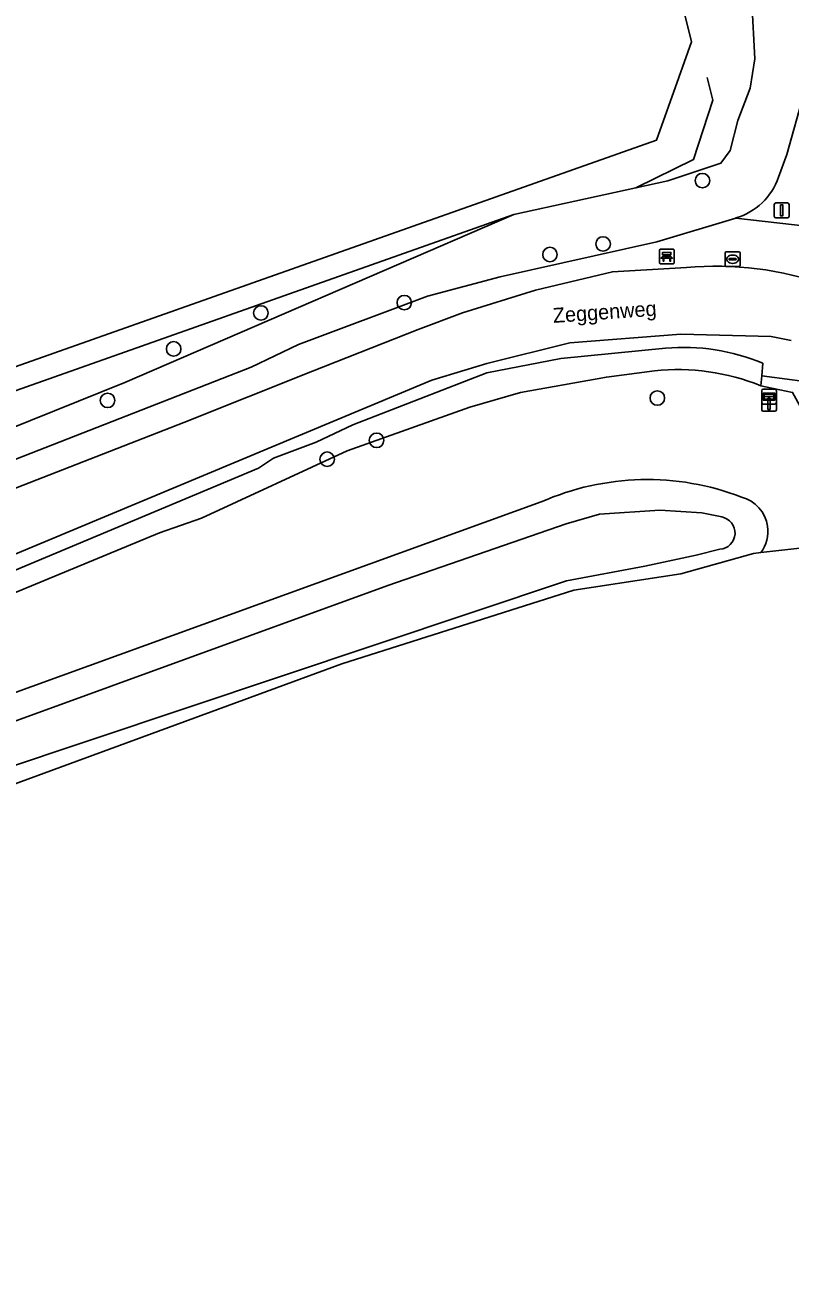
# Model space of a CAD drawing. Extents: x 164494 to 166241, y 382475 to 384495.
# Drawn here: x 164889.5 to 164941, y 383419.5 to 383503.5 of the extents above; entities that cross this region are included whole.
import ezdxf

# ---------------------------------------------------------------- set-up
doc = ezdxf.new("R2010")
doc.units = 0
for name, color, linetype in [('IMGEO_Afsluitpaal', 7, 'Continuous'), ('IMGEO_Bank', 7, 'Continuous'), ('IMGEO_Boom', 7, 'Continuous'), ('IMGEO_Bouwland', 7, 'Continuous'), ('IMGEO_Duiker', 7, 'Continuous'), ('IMGEO_Erf', 7, 'Continuous'), ('IMGEO_Grasland_overig', 7, 'Continuous'), ('IMGEO_Groenvoorziening', 7, 'Continuous'), ('IMGEO_Hek', 7, 'Continuous'), ('IMGEO_Informatiebord', 7, 'Continuous'), ('IMGEO_Loofbos', 7, 'Continuous'), ('IMGEO_Oever', 7, 'Continuous'), ('IMGEO_Openbare_ruimte_label', 7, 'Continuous'), ('IMGEO_Rijbaan_lokaal_halfverhard', 7, 'Continuous'), ('IMGEO_Rioolput', 7, 'Continuous'), ('IMGEO_Waterloop', 7, 'Continuous')]:
    doc.layers.add(name, color=color, linetype=linetype)

msp = doc.modelspace()

# ---------------------------------------------------------------- linework, layer by layer
at = {"layer": 'IMGEO_Afsluitpaal'}
for p, q in [((164939.975, 383490.643), (164939.975, 383491.443)), ((164939.975, 383491.443), (164939.975, 383490.643)), ((164940.075, 383491.543), (164940.865, 383491.543)), ((164940.865, 383491.543), (164940.075, 383491.543)), ((164940.965, 383491.443), (164940.965, 383490.643)), ((164940.965, 383490.643), (164940.965, 383491.443)), ((164940.865, 383490.543), (164940.075, 383490.543)), ((164940.075, 383490.543), (164940.865, 383490.543)), ((164939.126, 383477.607), (164939.126, 383478.407)), ((164939.126, 383478.407), (164939.126, 383477.607)), ((164939.226, 383478.507), (164940.016, 383478.507)), ((164940.016, 383478.507), (164939.226, 383478.507)), ((164940.116, 383478.407), (164940.116, 383477.607)), ((164940.116, 383477.607), (164940.116, 383478.407)), ((164940.016, 383477.507), (164939.226, 383477.507)), ((164939.226, 383477.507), (164940.016, 383477.507))]:
    msp.add_line(p, q, dxfattribs=at)
for points in [[(164940.395, 383491.418), (164940.545, 383491.418), (164940.545, 383490.668), (164940.395, 383490.668), (164940.395, 383491.418)], [(164939.546, 383478.382), (164939.696, 383478.382), (164939.696, 383477.632), (164939.546, 383477.632), (164939.546, 383478.382)]]:
    msp.add_lwpolyline(points, dxfattribs=at)
for centre, start, end in [((164940.075, 383491.443), 90, 180), ((164940.075, 383491.443), 90, 180), ((164940.865, 383491.443), 0, 90), ((164940.865, 383491.443), 360, 90), ((164940.075, 383490.643), 180, 270), ((164940.075, 383490.643), 180, 270), ((164940.865, 383490.643), 270, 0), ((164940.865, 383490.643), 270, 0), ((164939.226, 383478.407), 90, 180), ((164939.226, 383478.407), 90, 180), ((164940.016, 383478.407), 0, 90), ((164940.016, 383478.407), 360, 90), ((164939.226, 383477.607), 180, 270), ((164939.226, 383477.607), 180, 270), ((164940.016, 383477.607), 270, 0), ((164940.016, 383477.607), 270, 0)]:
    msp.add_arc(centre, 0.1, start, end, dxfattribs=at)
at = {"layer": 'IMGEO_Bank'}
for p, q in [((164932.241, 383487.508), (164932.241, 383488.349)), ((164932.241, 383488.349), (164932.241, 383487.508)), ((164932.316, 383488.433), (164933.157, 383488.433)), ((164933.157, 383488.433), (164932.316, 383488.433)), ((164933.241, 383488.358), (164933.241, 383487.517)), ((164933.241, 383487.517), (164933.241, 383488.358)), ((164932.938, 383487.831), (164932.545, 383487.831)), ((164932.55, 383487.939), (164932.55, 383488.045)), ((164932.594, 383488.045), (164932.594, 383487.939)), ((164932.882, 383488.051), (164932.6, 383488.051)), ((164932.6, 383487.933), (164932.882, 383487.933)), ((164932.888, 383487.939), (164932.888, 383488.045)), ((164932.932, 383488.045), (164932.932, 383487.939)), ((164933.166, 383487.433), (164932.325, 383487.433)), ((164932.325, 383487.433), (164933.166, 383487.433))]:
    msp.add_line(p, q, dxfattribs=at)
for points in [[(164932.488, 383487.831), (164932.346, 383487.831), (164932.458, 383487.933), (164932.544, 383487.933)], [(164932.544, 383488.051), (164932.458, 383488.051), (164932.458, 383488.212), (164933.021, 383488.212), (164933.021, 383488.051), (164932.938, 383488.051)], [(164932.538, 383487.824), (164932.538, 383487.617), (164932.495, 383487.617), (164932.495, 383487.824)], [(164932.938, 383487.933), (164933.021, 383487.933), (164933.133, 383487.831), (164932.994, 383487.831)], [(164932.988, 383487.824), (164932.988, 383487.617), (164932.944, 383487.617), (164932.944, 383487.824)]]:
    msp.add_lwpolyline(points, dxfattribs=at)
for centre, radius, start, end in [((164932.319, 383488.355), 0.0779, 92.4484, 184.28452), ((164932.319, 383488.355), 0.0779, 92.4484, 184.28452), ((164933.163, 383488.355), 0.0779, 2.4484, 94.28452), ((164933.163, 383488.355), 0.0779, 2.4484, 94.28452), ((164932.319, 383487.511), 0.0779, 182.4484, 274.28452), ((164932.319, 383487.511), 0.0779, 182.4484, 274.28452), ((164932.488, 383487.824), 0.00671, 2.89567, 87.10433), ((164932.545, 383487.824), 0.00671, 92.89567, 177.10433), ((164932.543, 383488.044), 0.00671, 2.89567, 87.10433), ((164932.543, 383487.94), 0.00671, 272.89567, 357.10433), ((164932.6, 383488.044), 0.00671, 92.89567, 177.10433), ((164932.6, 383487.94), 0.00671, 182.89567, 267.10433), ((164932.882, 383488.044), 0.00671, 2.89567, 87.10433), ((164932.882, 383487.94), 0.00671, 272.89567, 357.10433), ((164932.939, 383488.044), 0.00671, 92.89567, 177.10433), ((164932.939, 383487.94), 0.00671, 182.89567, 267.10433), ((164932.937, 383487.824), 0.00671, 2.89567, 87.10433), ((164932.994, 383487.824), 0.00671, 92.89567, 177.10433), ((164933.163, 383487.511), 0.0779, 272.4484, 4.28452), ((164933.163, 383487.511), 0.0779, 272.4484, 4.28452)]:
    msp.add_arc(centre, radius, start, end, dxfattribs=at)
at = {"layer": 'IMGEO_Boom'}
for centre in [(164935.137, 383493.047), (164928.449, 383488.778), (164924.872, 383488.067), (164915.068, 383484.828), (164905.413, 383484.132), (164899.542, 383481.709), (164895.093, 383478.243), (164932.1, 383478.4), (164913.202, 383475.553), (164909.875, 383474.281)]:
    msp.add_circle(centre, 0.489, dxfattribs=at)
at = {"layer": 'IMGEO_Bouwland'}
for points in [[(165060.094, 383385.823), (165046.933, 383390.448), (165039.93, 383393.368), (165039.139, 383393.397), (165024.547, 383396.41), (165016.215, 383401.117), (164994.138, 383419.758), (164976.25, 383437.136), (164945.936, 383468.751), (164939.064, 383467.989)], [(164939.064, 383467.989), (164938.58, 383467.935), (164933.685, 383466.564), (164926.474, 383465.463), (164910.854, 383460.501), (164868.575, 383444.955), (164868.931, 383444.423), (164876.262, 383433.486), (164912.566, 383384.323), (164914.978, 383381.056), (164915.281, 383377.04), (164913.179, 383375.78), (164908.171, 383370.539), (164912.922, 383363.364), (164915.309, 383360.31), (164919.551, 383354.884)]]:
    msp.add_lwpolyline(points, dxfattribs=at)
at = {"layer": 'IMGEO_Duiker'}
msp.add_lwpolyline([(164939.126, 383479.906), (164941.181, 383479.625), (164943.19, 383479.35), (164944.181, 383479.214)], dxfattribs=at)
at = {"layer": 'IMGEO_Erf'}
msp.add_lwpolyline([(164808.728, 383571.245), (164817.843, 383532.831), (164823.417, 383510.069), (164826.418, 383500), (164826.994, 383498.067), (164827.455, 383497.281), (164829.018, 383493.887), (164829.882, 383491.714), (164830.694, 383489.822), (164842.176, 383463.06), (164852.192, 383463.714), (164863.576, 383467.094), (164868.741, 383468.628), (164874.88, 383470.847), (164878.913, 383472.472), (164896.265, 383479.453), (164922.439, 383490.759), (164883.7, 383477.062), (164883.266, 383478.533), (164932.039, 383495.768), (164933.543, 383500), (164934.392, 383502.389), (164920.621, 383557.769), (164914.456, 383581.898)], dxfattribs=at)
at = {"layer": 'IMGEO_Grasland_overig'}
for points in [[(164941.103, 383482.279), (164939.754, 383482.543), (164933.677, 383482.698), (164926.219, 383482.116), (164920.619, 383480.729), (164916.918, 383479.598), (164886.419, 383466.871)], [(164852.502, 383453.533), (164852.877, 383452.823), (164853.207, 383452.199), (164857.558, 383455.915), (164857.419, 383456.458), (164857.229, 383457.202), (164860.608, 383458.332), (164870.476, 383460.687), (164880.047, 383463.612), (164886.717, 383465.911), (164905.253, 383473.685), (164906.253, 383474.343), (164909.134, 383475.436), (164911.595, 383476.59), (164920.618, 383480.089), (164925.597, 383481.057), (164932.651, 383481.754)], [(164931.914, 383480.237), (164928.674, 383479.81), (164922.894, 383478.784), (164919.474, 383477.792), (164911.232, 383474.851), (164901.408, 383470.314), (164898.593, 383469.326), (164887.355, 383464.67), (164880.544, 383462.211), (164871.064, 383459.446), (164857.558, 383455.915), (164853.207, 383452.199), (164852.098, 383451.058)], [(164939.195, 383480.74), (164939.126, 383479.906), (164939.069, 383479.227), (164941.206, 383478.776)], [(165099.425, 383315.013), (165092.197, 383334.924), (165086.24, 383357.128), (165076.785, 383375.884), (165072.749, 383381.958), (165062.554, 383397.301), (165051.511, 383396.474), (165026.953, 383397.574), (165014.572, 383404.259), (164992.612, 383424.036), (164945.886, 383470.277), (164941.206, 383478.776), (164939.069, 383479.227)], [(164865.347, 383449.105), (164871.03, 383452.109), (164924.289, 383471.404)], [(164939.064, 383467.989), (164945.936, 383468.751), (164976.25, 383437.136), (164994.138, 383419.758), (165016.215, 383401.117), (165024.547, 383396.41), (165039.139, 383393.397), (165039.93, 383393.368), (165059.663, 383392.644), (165063.093, 383390.374), (165077.781, 383368.198), (165082.253, 383356.239), (165083.125, 383346.054), (165094.168, 383312.876)]]:
    msp.add_lwpolyline(points, dxfattribs=at)
for centre, radius, start, end in [((164933.902, 383468.201), 13.611, 67.11233, 95.27167), ((164933.479, 383465.476), 14.844, 67.87835, 96.05208), ((164931.425, 383455.265), 17.646, 68.94552, 113.85174), ((164937.164, 383469.428), 2.381, 8.07648, 75.41405), ((164937.16, 383469.427), 2.386, 322.94455, 8.10314)]:
    msp.add_arc(centre, radius, start, end, dxfattribs=at)
at = {"layer": 'IMGEO_Groenvoorziening'}
for points in [[(164937.381, 383490.527), (164944.305, 383489.733), (164944.349, 383489.717), (164944.525, 383491.737), (164942.432, 383502.496)], [(164941.953, 383498.889), (164940.813, 383494.812), (164940.251, 383493.269)], [(164949.691, 383487.781), (164946.787, 383488.862), (164944.349, 383489.717), (164944.305, 383489.733), (164937.381, 383490.527), (164932.069, 383488.924), (164921.513, 383486.57), (164916.624, 383485.254), (164907.947, 383482), (164904.766, 383480.487), (164879.529, 383470.631), (164869.248, 383466.838), (164852.63, 383462.833), (164843.612, 383461.437), (164843.123, 383461.582), (164842.523, 383461.759), (164839.074, 383465.785), (164838.555, 383466.953), (164835.287, 383473.588), (164828.161, 383491.006), (164829.882, 383491.714)], [(164842.398, 383460.205), (164843.275, 383459.916), (164844.449, 383459.742), (164846.387, 383459.64), (164853.943, 383461.373), (164860.735, 383462.825), (164865.962, 383464.299), (164869.596, 383465.427), (164878.966, 383468.472), (164900.223, 383476.754), (164908.882, 383480.203), (164916, 383483.026), (164918.976, 383484.138), (164923.891, 383485.657), (164929.074, 383486.908), (164934.056, 383487.198)]]:
    msp.add_lwpolyline(points, dxfattribs=at)
for centre, radius, start, end in [((164936.207, 383494.629), 4.266, 285.97187, 341.41495), ((164936.018, 383464.848), 22.436, 70.63027, 95.01621)]:
    msp.add_arc(centre, radius, start, end, dxfattribs=at)
at = {"layer": 'IMGEO_Hek'}
for points in [[(164930.655, 383492.556), (164934.54, 383494.463), (164935.833, 383498.473), (164935.453, 383500)], [(164883.266, 383478.533), (164883.7, 383477.062), (164922.439, 383490.759)]]:
    msp.add_lwpolyline(points, dxfattribs=at)
at = {"layer": 'IMGEO_Informatiebord'}
for p, q in [((164939.126, 383478.096), (164939.126, 383478.896)), ((164939.126, 383478.896), (164939.126, 383478.096)), ((164939.226, 383478.996), (164940.016, 383478.996)), ((164940.016, 383478.996), (164939.226, 383478.996)), ((164940.116, 383478.896), (164940.116, 383478.096)), ((164940.116, 383478.096), (164940.116, 383478.896)), ((164940.016, 383477.996), (164939.226, 383477.996)), ((164939.226, 383477.996), (164940.016, 383477.996))]:
    msp.add_line(p, q, dxfattribs=at)
for points in [[(164939.227, 383478.728), (164940.015, 383478.728), (164940.015, 383478.264), (164939.227, 383478.264), (164939.227, 383478.728)], [(164939.292, 383478.663), (164939.292, 383478.329), (164939.95, 383478.329), (164939.95, 383478.663), (164939.292, 383478.663)]]:
    msp.add_lwpolyline(points, dxfattribs=at)
for centre, start, end in [((164939.226, 383478.896), 90, 180), ((164939.226, 383478.896), 90, 180), ((164940.016, 383478.896), 0, 90), ((164940.016, 383478.896), 360, 90), ((164939.226, 383478.096), 180, 270), ((164939.226, 383478.096), 180, 270), ((164940.016, 383478.096), 270, 0), ((164940.016, 383478.096), 270, 0)]:
    msp.add_arc(centre, 0.1, start, end, dxfattribs=at)
at = {"layer": 'IMGEO_Loofbos'}
msp.add_lwpolyline([(164914.456, 383581.898), (164920.621, 383557.769), (164934.392, 383502.389), (164933.543, 383500), (164932.039, 383495.768), (164883.266, 383478.533), (164883.7, 383477.062), (164922.439, 383490.759), (164930.655, 383492.556), (164932.817, 383493.02), (164936.387, 383494.227), (164936.999, 383495.076), (164937.523, 383497.092), (164938.348, 383499.27), (164938.661, 383501.255), (164938.474, 383505.068), (164937.044, 383511.773), (164933.129, 383526.073), (164927.327, 383547.127), (164923.107, 383561.975), (164919.177, 383578.107)], dxfattribs=at)
at = {"layer": 'IMGEO_Oever'}
for points in [[(164924.289, 383471.404), (164871.03, 383452.109), (164865.347, 383449.105)], [(164925.96, 383469.938), (164928.214, 383470.571), (164932.28, 383470.839), (164935.094, 383470.661), (164936.435, 383470.393)], [(164867.624, 383448.92), (164913.965, 383465.771), (164925.96, 383469.938)], [(164936.301, 383468.215), (164934.715, 383467.812), (164931.252, 383467.086), (164925.991, 383466.081), (164874.646, 383448.92), (164868.943, 383447.047), (164867.326, 383444.749), (164867.752, 383443.303), (164868.773, 383440.664), (164905.795, 383391.218), (164911.909, 383382.143), (164910.33, 383380.925), (164865.199, 383442.664), (164864.348, 383444.622)], [(164863.009, 383441.79), (164877.214, 383421.031), (164908.784, 383379.416), (164910.203, 383379.262), (164913.003, 383381.452), (164913.106, 383382.53), (164912.566, 383384.323), (164876.262, 383433.486), (164868.931, 383444.423), (164868.575, 383444.955), (164910.854, 383460.501), (164926.474, 383465.463), (164933.685, 383466.564), (164938.58, 383467.935), (164939.064, 383467.989)]]:
    msp.add_lwpolyline(points, dxfattribs=at)
for centre, radius, start, end in [((164931.425, 383455.265), 17.646, 68.94552, 113.85174), ((164937.164, 383469.428), 2.381, 8.07648, 75.41405), ((164936.237, 383469.312), 1.099, 273.31946, 79.63924), ((164937.16, 383469.427), 2.386, 322.94455, 8.10314)]:
    msp.add_arc(centre, radius, start, end, dxfattribs=at)
at = {"layer": 'IMGEO_Rijbaan_lokaal_halfverhard'}
for points in [[(164934.056, 383487.198), (164929.074, 383486.908), (164923.891, 383485.657), (164918.976, 383484.138), (164916, 383483.026), (164908.882, 383480.203), (164900.223, 383476.754), (164878.966, 383468.472)], [(164886.419, 383466.871), (164916.918, 383479.598), (164920.619, 383480.729), (164926.219, 383482.116), (164933.677, 383482.698), (164939.754, 383482.543), (164941.103, 383482.279)]]:
    msp.add_lwpolyline(points, dxfattribs=at)
msp.add_arc((164936.018, 383464.848), 22.436, 70.63027, 95.01621, dxfattribs=at)
at = {"layer": 'IMGEO_Rioolput'}
for p, q in [((164936.67, 383487.325), (164936.67, 383488.177)), ((164936.745, 383488.251), (164937.597, 383488.251)), ((164936.929, 383487.745), (164936.929, 383487.757)), ((164937.367, 383487.708), (164936.969, 383487.708)), ((164936.972, 383487.794), (164937.37, 383487.794)), ((164937.181, 383487.471), (164937.156, 383487.471)), ((164937.158, 383488.031), (164937.183, 383488.031)), ((164937.413, 383487.757), (164937.413, 383487.745)), ((164937.671, 383488.177), (164937.671, 383487.325)), ((164937.597, 383487.251), (164936.745, 383487.251))]:
    msp.add_line(p, q, dxfattribs=at)
for points in [[(164936.67, 383487.325), (164936.67, 383488.177)], [(164936.745, 383488.251), (164937.597, 383488.251)], [(164937.671, 383488.177), (164937.671, 383487.325)], [(164937.597, 383487.251), (164936.745, 383487.251)]]:
    msp.add_lwpolyline(points, dxfattribs=at)
for centre, radius, start, end in [((164936.747, 383488.175), 0.0765, 91.55205, 178.44795), ((164936.747, 383488.175), 0.0765, 91.55205, 178.44795), ((164936.969, 383487.754), 0.0403, 85.87752, 175.75265), ((164936.966, 383487.744), 0.0366, 178.93798, 274.71019), ((164937.37, 383487.751), 0.043, 264.86636, 352.45326), ((164937.374, 383487.756), 0.0386, 1.73085, 96.63898), ((164937.595, 383488.175), 0.0765, 1.55205, 88.44795), ((164937.595, 383488.175), 0.0765, 1.55205, 88.44795), ((164936.747, 383487.327), 0.0765, 181.55205, 268.44795), ((164936.747, 383487.327), 0.0765, 181.55205, 268.44795), ((164937.595, 383487.327), 0.0765, 271.55205, 358.44795), ((164937.595, 383487.327), 0.0765, 271.55205, 358.44795)]:
    msp.add_arc(centre, radius, start, end, dxfattribs=at)
for centre, major_axis, ratio, start_param, end_param in [((164937.157, 383487.751), (-0.387, 0.002), 0.722429, 4.712389, 7.853982), ((164937.182, 383487.751), (-0.39, 0.002), 0.717154, 1.570796, 4.712389)]:
    msp.add_ellipse(centre, major_axis=major_axis, ratio=ratio, start_param=start_param, end_param=end_param, dxfattribs=at)
at = {"layer": 'IMGEO_Waterloop'}
for points in [[(164938.474, 383505.068), (164938.661, 383501.255), (164938.348, 383499.27), (164937.523, 383497.092), (164936.999, 383495.076), (164936.387, 383494.227), (164932.817, 383493.02), (164930.655, 383492.556), (164922.439, 383490.759), (164896.265, 383479.453), (164878.913, 383472.472)], [(164940.251, 383493.269), (164940.813, 383494.812), (164941.953, 383498.889)], [(164879.529, 383470.631), (164904.766, 383480.487), (164907.947, 383482), (164916.624, 383485.254), (164921.513, 383486.57), (164932.069, 383488.924), (164937.381, 383490.527)], [(164932.651, 383481.754), (164925.597, 383481.057), (164920.618, 383480.089), (164911.595, 383476.59), (164909.134, 383475.436), (164906.253, 383474.343), (164905.253, 383473.685), (164886.717, 383465.911), (164880.047, 383463.612), (164870.476, 383460.687), (164860.608, 383458.332), (164857.229, 383457.202), (164857.419, 383456.458), (164857.558, 383455.915), (164871.064, 383459.446), (164880.544, 383462.211), (164887.355, 383464.67), (164898.593, 383469.326), (164901.408, 383470.314), (164911.232, 383474.851), (164919.474, 383477.792), (164922.894, 383478.784), (164928.674, 383479.81), (164931.914, 383480.237)], [(164939.069, 383479.227), (164939.126, 383479.906), (164939.195, 383480.74)], [(164936.435, 383470.393), (164935.094, 383470.661), (164932.28, 383470.839), (164928.214, 383470.571), (164925.96, 383469.938), (164913.965, 383465.771), (164867.624, 383448.92)], [(164910.33, 383380.925), (164911.909, 383382.143), (164905.795, 383391.218), (164868.773, 383440.664), (164867.752, 383443.303), (164867.326, 383444.749), (164868.943, 383447.047), (164874.646, 383448.92), (164925.991, 383466.081), (164931.252, 383467.086), (164934.715, 383467.812), (164936.301, 383468.215)]]:
    msp.add_lwpolyline(points, dxfattribs=at)
for centre, radius, start, end in [((164936.207, 383494.629), 4.266, 285.97187, 341.41495), ((164933.902, 383468.201), 13.611, 67.11233, 95.27167), ((164933.479, 383465.476), 14.844, 67.87835, 96.05208), ((164936.237, 383469.312), 1.099, 273.31946, 79.63924)]:
    msp.add_arc(centre, radius, start, end, dxfattribs=at)

# ---------------------------------------------------------------- texts
at = {"layer": 'IMGEO_Openbare_ruimte_label'}
msp.add_text('Zeggenweg', height=1, rotation=4.01217, dxfattribs=at).set_placement((164925.106, 383483.46))

doc.saveas('drawing.dxf')
